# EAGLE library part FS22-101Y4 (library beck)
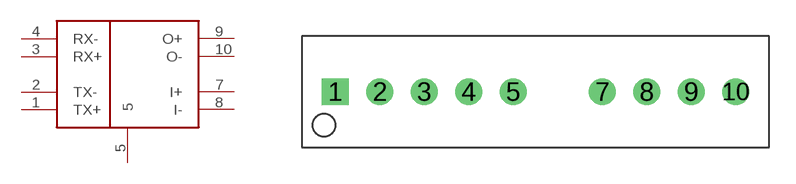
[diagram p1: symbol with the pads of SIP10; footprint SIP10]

Designator prefix -

## FS22-101Y4SIP10  [SIP10]
1  TX+  in
2  TX-  in
3  RX+  out
4  RX-  out
5  5  pas
7  I+  in
8  I-  in
9  O+  out
10  O-  out

## Footprint SIP10 (pad centres in mm)
drill 1.016 square: 1 -12.7,0
drill 1.016 round: 2 -10.16,0; 3 -7.62,0; 4 -5.08,0; 5 -2.54,0; 7 2.54,0; 8 5.08,0; 9 7.62,0; 10 10.16,0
